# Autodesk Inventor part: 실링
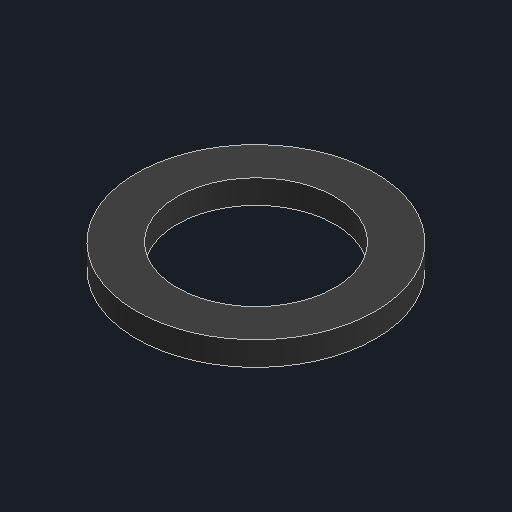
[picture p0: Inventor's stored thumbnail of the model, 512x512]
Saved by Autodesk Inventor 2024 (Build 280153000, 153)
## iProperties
Created: 2025-02
Part Number: 실링
Material: 고무
Document SubType Name: Modeling
Designer: kh_501
Density: 0.93 g/cm^3
Appearance: 기본값
Author: jhkim
Sending System: Autodesk Inventor 2025
Preprocessor: ST-DEVELOPER v20
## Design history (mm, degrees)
node "실링1"
node "솔리드2"
node "솔리드1"
